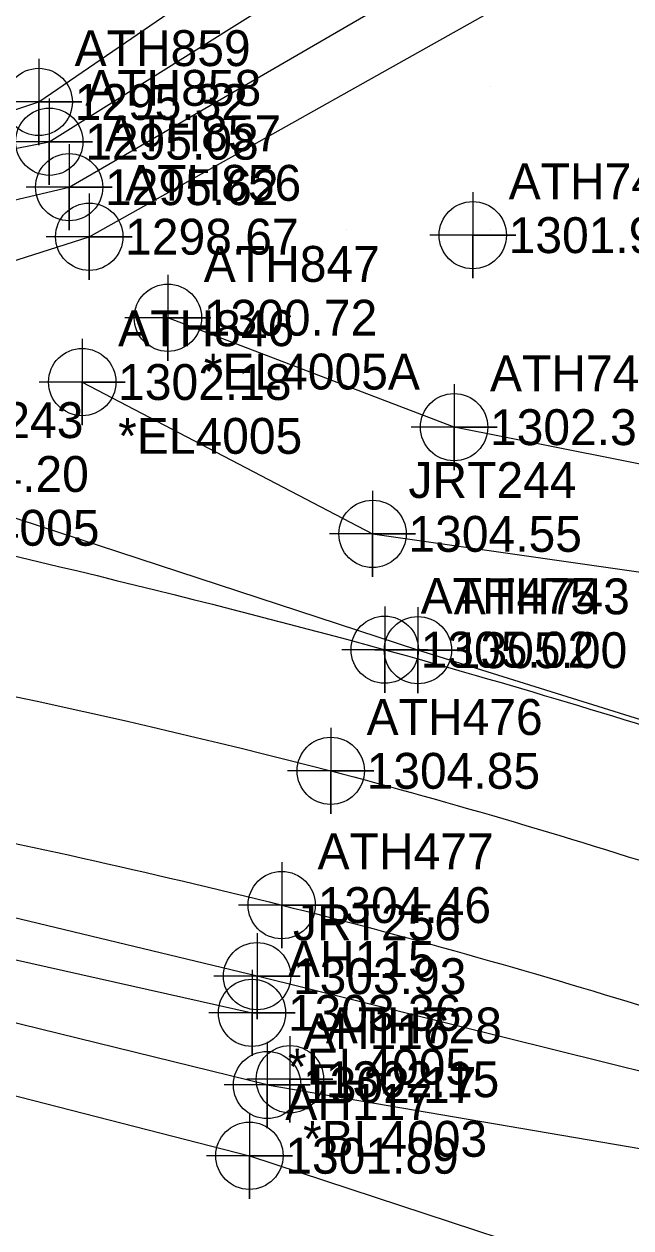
# Model space of a CAD drawing. Extents: x 1234484 to 1235382, y 695050 to 695510.
# Drawn here: x 1235007.5 to 1235049.8, y 695270.5 to 695354.3 of the extents above; entities that cross this region are included whole.
import ezdxf

# ---------------------------------------------------------------- set-up
doc = ezdxf.new("R2010")
doc.units = 0
for name, color, linetype in [('Exist DTM Breakline', 7, 'Continuous'), ('Exist DTM Breakline Cogo Comment', 7, 'Continuous'), ('Exist DTM Breakline Cogo Elevation', 7, 'Continuous'), ('Exist DTM Breakline Cogo Number', 7, 'Continuous'), ('Exist DTM Breakline Cogo Point CELL', 7, 'Continuous'), ('Exist DTM Breakline Underwater', 7, 'Continuous'), ('Exist DTM Crownline', 7, 'Continuous'), ('Exist DTM Crownline Cogo Elevation', 7, 'Continuous'), ('Exist DTM Crownline Cogo Number', 7, 'Continuous'), ('Exist DTM Crownline Cogo Point CELL', 7, 'Continuous'), ('Exist DTM Drainline Cogo Comment', 7, 'Continuous'), ('Exist DTM Drainline Cogo Elevation', 7, 'Continuous'), ('Exist DTM Drainline Cogo Number', 7, 'Continuous'), ('Exist DTM Drainline Cogo Point CELL', 7, 'Continuous'), ('Exist DTM QL2 LIDAR Elevation Point', 7, 'Continuous'), ('Exist DTM Regular Point CELL', 7, 'Continuous'), ('Exist DTM Regular Point Cogo Elevation', 7, 'Continuous'), ('Exist DTM Regular Point Cogo Number', 7, 'Continuous'), ('Exist DTM Regular Point Underwater CELL', 7, 'Continuous'), ('Exist DTM Regular Point Underwater Cogo Elevation', 7, 'Continuous'), ('Exist DTM Regular Point Underwater Cogo Number', 7, 'Continuous'), ('Exist Hydro Stream or Body of Water', 7, 'Continuous'), ('Exist Roads EOP', 7, 'Continuous'), ('Exist Roads EOP Cogo Elevation', 7, 'Continuous'), ('Exist Roads EOP Cogo Number', 7, 'Continuous'), ('Exist Roads EOP Cogo Point CELL', 7, 'Continuous')]:
    doc.layers.add(name, color=color, linetype=linetype)

msp = doc.modelspace()

# ---------------------------------------------------------------- linework, layer by layer
at = {"layer": 'Exist DTM Breakline'}
for points in [[(1234978.66, 695327.276), (1234992.748, 695333.364), (1235012.047, 695339.528), (1235045.835, 695358.491), (1235079.523, 695374.606), (1235097.5, 695391.337)], [(1235082.217, 695317.363), (1235037.46, 695326.259), (1235017.524, 695333.883)], [(1235011.557, 695329.402), (1235031.782, 695318.825), (1235070.444, 695313.308)], [(1235319.256, 695177.55), (1235278.534, 695201.47), (1235237.781, 695224.217), (1235188.481, 695250.698), (1235134.96, 695275.849), (1235082.338, 695295.901), (1235034.938, 695310.723), (1234997.435, 695322.999)], [(1235258.778, 695187.05), (1235221.35, 695207.416), (1235173.519, 695232.644), (1235125.211, 695254.804), (1235075.73, 695275.107), (1235023.735, 695288.012), (1234968.789, 695301.22)], [(1234957.627, 695296.648), (1234962.584, 695298.324), (1234974.436, 695296.452), (1235023.384, 695285.46)]]:
    msp.add_lwpolyline(points, dxfattribs=at)
at = {"layer": 'Exist DTM Breakline Cogo Point CELL'}
for points in [[(1235012.047, 695342.528), (1235012.047, 695336.528), (1235012.047, 695339.528), (1235015.047, 695339.528), (1235009.047, 695339.528)], [(1235017.524, 695336.883), (1235017.524, 695330.883), (1235017.524, 695333.883), (1235020.524, 695333.883), (1235014.524, 695333.883)], [(1235011.557, 695332.402), (1235011.557, 695326.402), (1235011.557, 695329.402), (1235014.557, 695329.402), (1235008.557, 695329.402)], [(1235037.46, 695329.259), (1235037.46, 695323.259), (1235037.46, 695326.259), (1235040.46, 695326.259), (1235034.46, 695326.259)], [(1235031.782, 695321.825), (1235031.782, 695315.825), (1235031.782, 695318.825), (1235034.782, 695318.825), (1235028.782, 695318.825)], [(1235034.938, 695313.723), (1235034.938, 695307.723), (1235034.938, 695310.723), (1235037.938, 695310.723), (1235031.938, 695310.723)], [(1235023.735, 695291.012), (1235023.735, 695285.012), (1235023.735, 695288.012), (1235026.735, 695288.012), (1235020.735, 695288.012)], [(1235023.384, 695288.46), (1235023.384, 695282.46), (1235023.384, 695285.46), (1235026.384, 695285.46), (1235020.384, 695285.46)], [(1235026.025, 695283.83), (1235026.025, 695277.83), (1235026.025, 695280.83), (1235029.025, 695280.83), (1235023.025, 695280.83)]]:
    msp.add_lwpolyline(points, dxfattribs=at)
for centre in [(1235012.047, 695339.528), (1235017.524, 695333.883), (1235011.557, 695329.402), (1235037.46, 695326.259), (1235031.782, 695318.825), (1235034.938, 695310.723), (1235023.735, 695288.012), (1235023.384, 695285.46), (1235026.025, 695280.83)]:
    msp.add_circle(centre, 2.344, dxfattribs=at)
at = {"layer": 'Exist DTM Breakline Underwater'}
for points in [[(1234766.421, 695209.389), (1234812.885, 695247.237), (1234843.411, 695272.621), (1234869.986, 695279.055), (1234895.378, 695289.036), (1234916.238, 695295.408), (1234934.131, 695306.081), (1234961.466, 695329.617), (1234991.436, 695342.664), (1235009.265, 695346.147), (1235040.352, 695365.623), (1235072.367, 695380.008), (1235092.174, 695396.335)], [(1234948.239, 695292.841), (1234952.805, 695292.84), (1234960.83, 695292.864), (1234972.599, 695288.481), (1235023.203, 695275.502), (1235056.399, 695264.585), (1235086.587, 695258.395), (1235121.582, 695234.941), (1235168.445, 695213.485), (1235191.313, 695204.186), (1235209.05, 695188.429), (1235246.922, 695166.749), (1235265.478, 695149.496)]]:
    msp.add_lwpolyline(points, dxfattribs=at)
at = {"layer": 'Exist DTM Crownline'}
msp.add_spline([(1234978.534, 695313.159), (1235028.867, 695302.317), (1235079.475, 695286.154), (1235130.202, 695265.942), (1235178.94, 695242.599), (1235226.8, 695217.474)], degree=3, dxfattribs=at)
at = {"layer": 'Exist DTM Crownline Cogo Point CELL'}
msp.add_lwpolyline([(1235028.867, 695305.317), (1235028.867, 695299.317), (1235028.867, 695302.317), (1235031.867, 695302.317), (1235025.867, 695302.317)], dxfattribs=at)
msp.add_circle((1235028.867, 695302.317), 2.344, dxfattribs=at)
at = {"layer": 'Exist DTM Drainline Cogo Point CELL'}
for points in [[(1235008.526, 695351.915), (1235008.526, 695345.915), (1235008.526, 695348.915), (1235011.526, 695348.915), (1235005.526, 695348.915)], [(1235010.649, 695345.979), (1235010.649, 695339.979), (1235010.649, 695342.979), (1235013.649, 695342.979), (1235007.649, 695342.979)], [(1235024.437, 695283.431), (1235024.437, 695277.431), (1235024.437, 695280.431), (1235027.437, 695280.431), (1235021.437, 695280.431)]]:
    msp.add_lwpolyline(points, dxfattribs=at)
for centre in [(1235008.526, 695348.915), (1235010.649, 695342.979), (1235024.437, 695280.431)]:
    msp.add_circle(centre, 2.344, dxfattribs=at)
at = {"layer": 'Exist DTM QL2 LIDAR Elevation Point'}
for p, q in [((1235040, 695350), (1235040, 695350)), ((1235030, 695340), (1235030, 695340)), ((1235040, 695340), (1235040, 695340)), ((1235040, 695330), (1235040, 695330))]:
    msp.add_line(p, q, dxfattribs=at)
at = {"layer": 'Exist DTM Regular Point CELL'}
msp.add_lwpolyline([(1235038.762, 695342.636), (1235038.762, 695336.636), (1235038.762, 695339.636), (1235041.762, 695339.636), (1235035.762, 695339.636)], dxfattribs=at)
msp.add_circle((1235038.762, 695339.636), 2.344, dxfattribs=at)
at = {"layer": 'Exist DTM Regular Point Underwater CELL'}
for points in [[(1235009.265, 695349.147), (1235009.265, 695343.147), (1235009.265, 695346.147), (1235012.265, 695346.147), (1235006.265, 695346.147)], [(1235023.203, 695278.502), (1235023.203, 695272.502), (1235023.203, 695275.502), (1235026.203, 695275.502), (1235020.203, 695275.502)]]:
    msp.add_lwpolyline(points, dxfattribs=at)
for centre in [(1235009.265, 695346.147), (1235023.203, 695275.502)]:
    msp.add_circle(centre, 2.344, dxfattribs=at)
at = {"layer": 'Exist Hydro Stream or Body of Water'}
for points in [[(1234766.439, 695214.543), (1234809.451, 695250.146), (1234840.783, 695273.683), (1234870.231, 695281.467), (1234894.384, 695292.767), (1234915.014, 695298.345), (1234929.933, 695306.511), (1234953.845, 695329.807), (1234986.204, 695341.472), (1235008.526, 695348.915), (1235037.336, 695368.653), (1235069.491, 695383.302), (1235088.448, 695400.861)], [(1234938.044, 695305.366), (1234971.304, 695328.94), (1234992.169, 695338.626), (1235010.649, 695342.979), (1235043.523, 695362.073), (1235076.562, 695377.561), (1235094.01, 695394.044)], [(1235024.437, 695280.431), (1234972.886, 695293.093), (1234963.03, 695297.482)], [(1235024.437, 695280.431), (1235058.02, 695274.707), (1235089.925, 695266.038), (1235123.219, 695251.801), (1235172.108, 695226.531), (1235193.345, 695212.706), (1235213.169, 695197.447), (1235252.346, 695179.593), (1235273.059, 695163.484)]]:
    msp.add_lwpolyline(points, dxfattribs=at)
at = {"layer": 'Exist Roads EOP'}
for points in [[(1234989.744, 695321.275), (1235032.632, 695310.758), (1235082.97, 695294.625), (1235134.247, 695274.482), (1235183.928, 695250.955), (1235232.115, 695225.68)], [(1234969.592, 695304.589), (1235025.451, 695292.964), (1235076.313, 695277.193), (1235126.218, 695256.569), (1235174.523, 695234.324), (1235222.247, 695208.988)]]:
    msp.add_spline(points, degree=3, dxfattribs=at)
at = {"layer": 'Exist Roads EOP Cogo Point CELL'}
for points in [[(1235032.632, 695313.758), (1235032.632, 695307.758), (1235032.632, 695310.758), (1235035.632, 695310.758), (1235029.632, 695310.758)], [(1235025.451, 695295.964), (1235025.451, 695289.964), (1235025.451, 695292.964), (1235028.451, 695292.964), (1235022.451, 695292.964)]]:
    msp.add_lwpolyline(points, dxfattribs=at)
for centre in [(1235032.632, 695310.758), (1235025.451, 695292.964)]:
    msp.add_circle(centre, 2.344, dxfattribs=at)

# ---------------------------------------------------------------- texts
at = {"layer": 'Exist DTM Breakline Cogo Comment'}
for s, p in [('*EL4005A', (1235020.024, 695328.883)), ('*EL4005', (1235014.057, 695324.402)), ('*BL4005', (1234999.935, 695317.999)), ('*EL4005', (1235025.884, 695280.46))]:
    msp.add_text(s, height=2.5, dxfattribs=at).set_placement(p)
at = {"layer": 'Exist DTM Breakline Cogo Elevation'}
for s, p in [('1298.67', (1235014.547, 695338.278)), ('1300.72', (1235020.024, 695332.633)), ('1302.18', (1235014.057, 695328.152)), ('1302.31', (1235039.96, 695325.009)), ('1304.20', (1234999.935, 695321.749)), ('1304.55', (1235034.282, 695317.575)), ('1305.00', (1235037.438, 695309.473)), ('1303.93', (1235026.235, 695286.762)), ('1303.36', (1235025.884, 695284.21)), ('1302.15', (1235028.525, 695279.58))]:
    msp.add_text(s, height=2.5, dxfattribs=at).set_placement(p)
at = {"layer": 'Exist DTM Breakline Cogo Number'}
for s, p in [('ATH856', (1235014.547, 695342.028)), ('ATH847', (1235020.024, 695336.383)), ('ATH846', (1235014.057, 695331.902)), ('ATH744', (1235039.96, 695328.759)), ('JRT243', (1234999.935, 695325.499)), ('JRT244', (1235034.282, 695321.325)), ('ATH743', (1235037.438, 695313.223)), ('JRT256', (1235026.235, 695290.512)), ('AH115', (1235025.884, 695287.96)), ('ATH728', (1235028.525, 695283.33))]:
    msp.add_text(s, height=2.5, dxfattribs=at).set_placement(p)
at = {"layer": 'Exist DTM Crownline Cogo Elevation'}
msp.add_text('1304.85', height=2.5, dxfattribs=at).set_placement((1235031.367, 695301.067))
at = {"layer": 'Exist DTM Crownline Cogo Number'}
msp.add_text('ATH476', height=2.5, dxfattribs=at).set_placement((1235031.367, 695304.817))
at = {"layer": 'Exist DTM Drainline Cogo Comment'}
msp.add_text('*BL4003', height=2.5, dxfattribs=at).set_placement((1235026.937, 695275.431))
at = {"layer": 'Exist DTM Drainline Cogo Elevation'}
for s, p in [('1295.32', (1235011.026, 695347.665)), ('1295.62', (1235013.149, 695341.729)), ('1302.17', (1235026.937, 695279.181))]:
    msp.add_text(s, height=2.5, dxfattribs=at).set_placement(p)
at = {"layer": 'Exist DTM Drainline Cogo Number'}
for s, p in [('ATH859', (1235011.026, 695351.415)), ('ATH857', (1235013.149, 695345.479)), ('AH116', (1235026.937, 695282.931))]:
    msp.add_text(s, height=2.5, dxfattribs=at).set_placement(p)
at = {"layer": 'Exist DTM Regular Point Cogo Elevation'}
msp.add_text('1301.97', height=2.5, dxfattribs=at).set_placement((1235041.262, 695338.386))
at = {"layer": 'Exist DTM Regular Point Cogo Number'}
msp.add_text('ATH745', height=2.5, dxfattribs=at).set_placement((1235041.262, 695342.136))
at = {"layer": 'Exist DTM Regular Point Underwater Cogo Elevation'}
for s, p in [('1295.08', (1235011.765, 695344.897)), ('1301.89', (1235025.703, 695274.252))]:
    msp.add_text(s, height=2.5, dxfattribs=at).set_placement(p)
at = {"layer": 'Exist DTM Regular Point Underwater Cogo Number'}
for s, p in [('ATH858', (1235011.765, 695348.647)), ('AH117', (1235025.703, 695278.002))]:
    msp.add_text(s, height=2.5, dxfattribs=at).set_placement(p)
at = {"layer": 'Exist Roads EOP Cogo Elevation'}
for s, p in [('1305.02', (1235035.132, 695309.508)), ('1304.46', (1235027.951, 695291.714))]:
    msp.add_text(s, height=2.5, dxfattribs=at).set_placement(p)
at = {"layer": 'Exist Roads EOP Cogo Number'}
for s, p in [('ATH475', (1235035.132, 695313.258)), ('ATH477', (1235027.951, 695295.464))]:
    msp.add_text(s, height=2.5, dxfattribs=at).set_placement(p)

doc.saveas('drawing.dxf')
